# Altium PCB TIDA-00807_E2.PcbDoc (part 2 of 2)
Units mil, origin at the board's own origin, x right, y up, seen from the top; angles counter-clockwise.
Board outline 2559.06 x 2559.06 mil, 2 copper layers (Top Layer, Bottom Layer), stack 62 mil thick; 165 components, 78 nets, 356 pads, 106 vias.
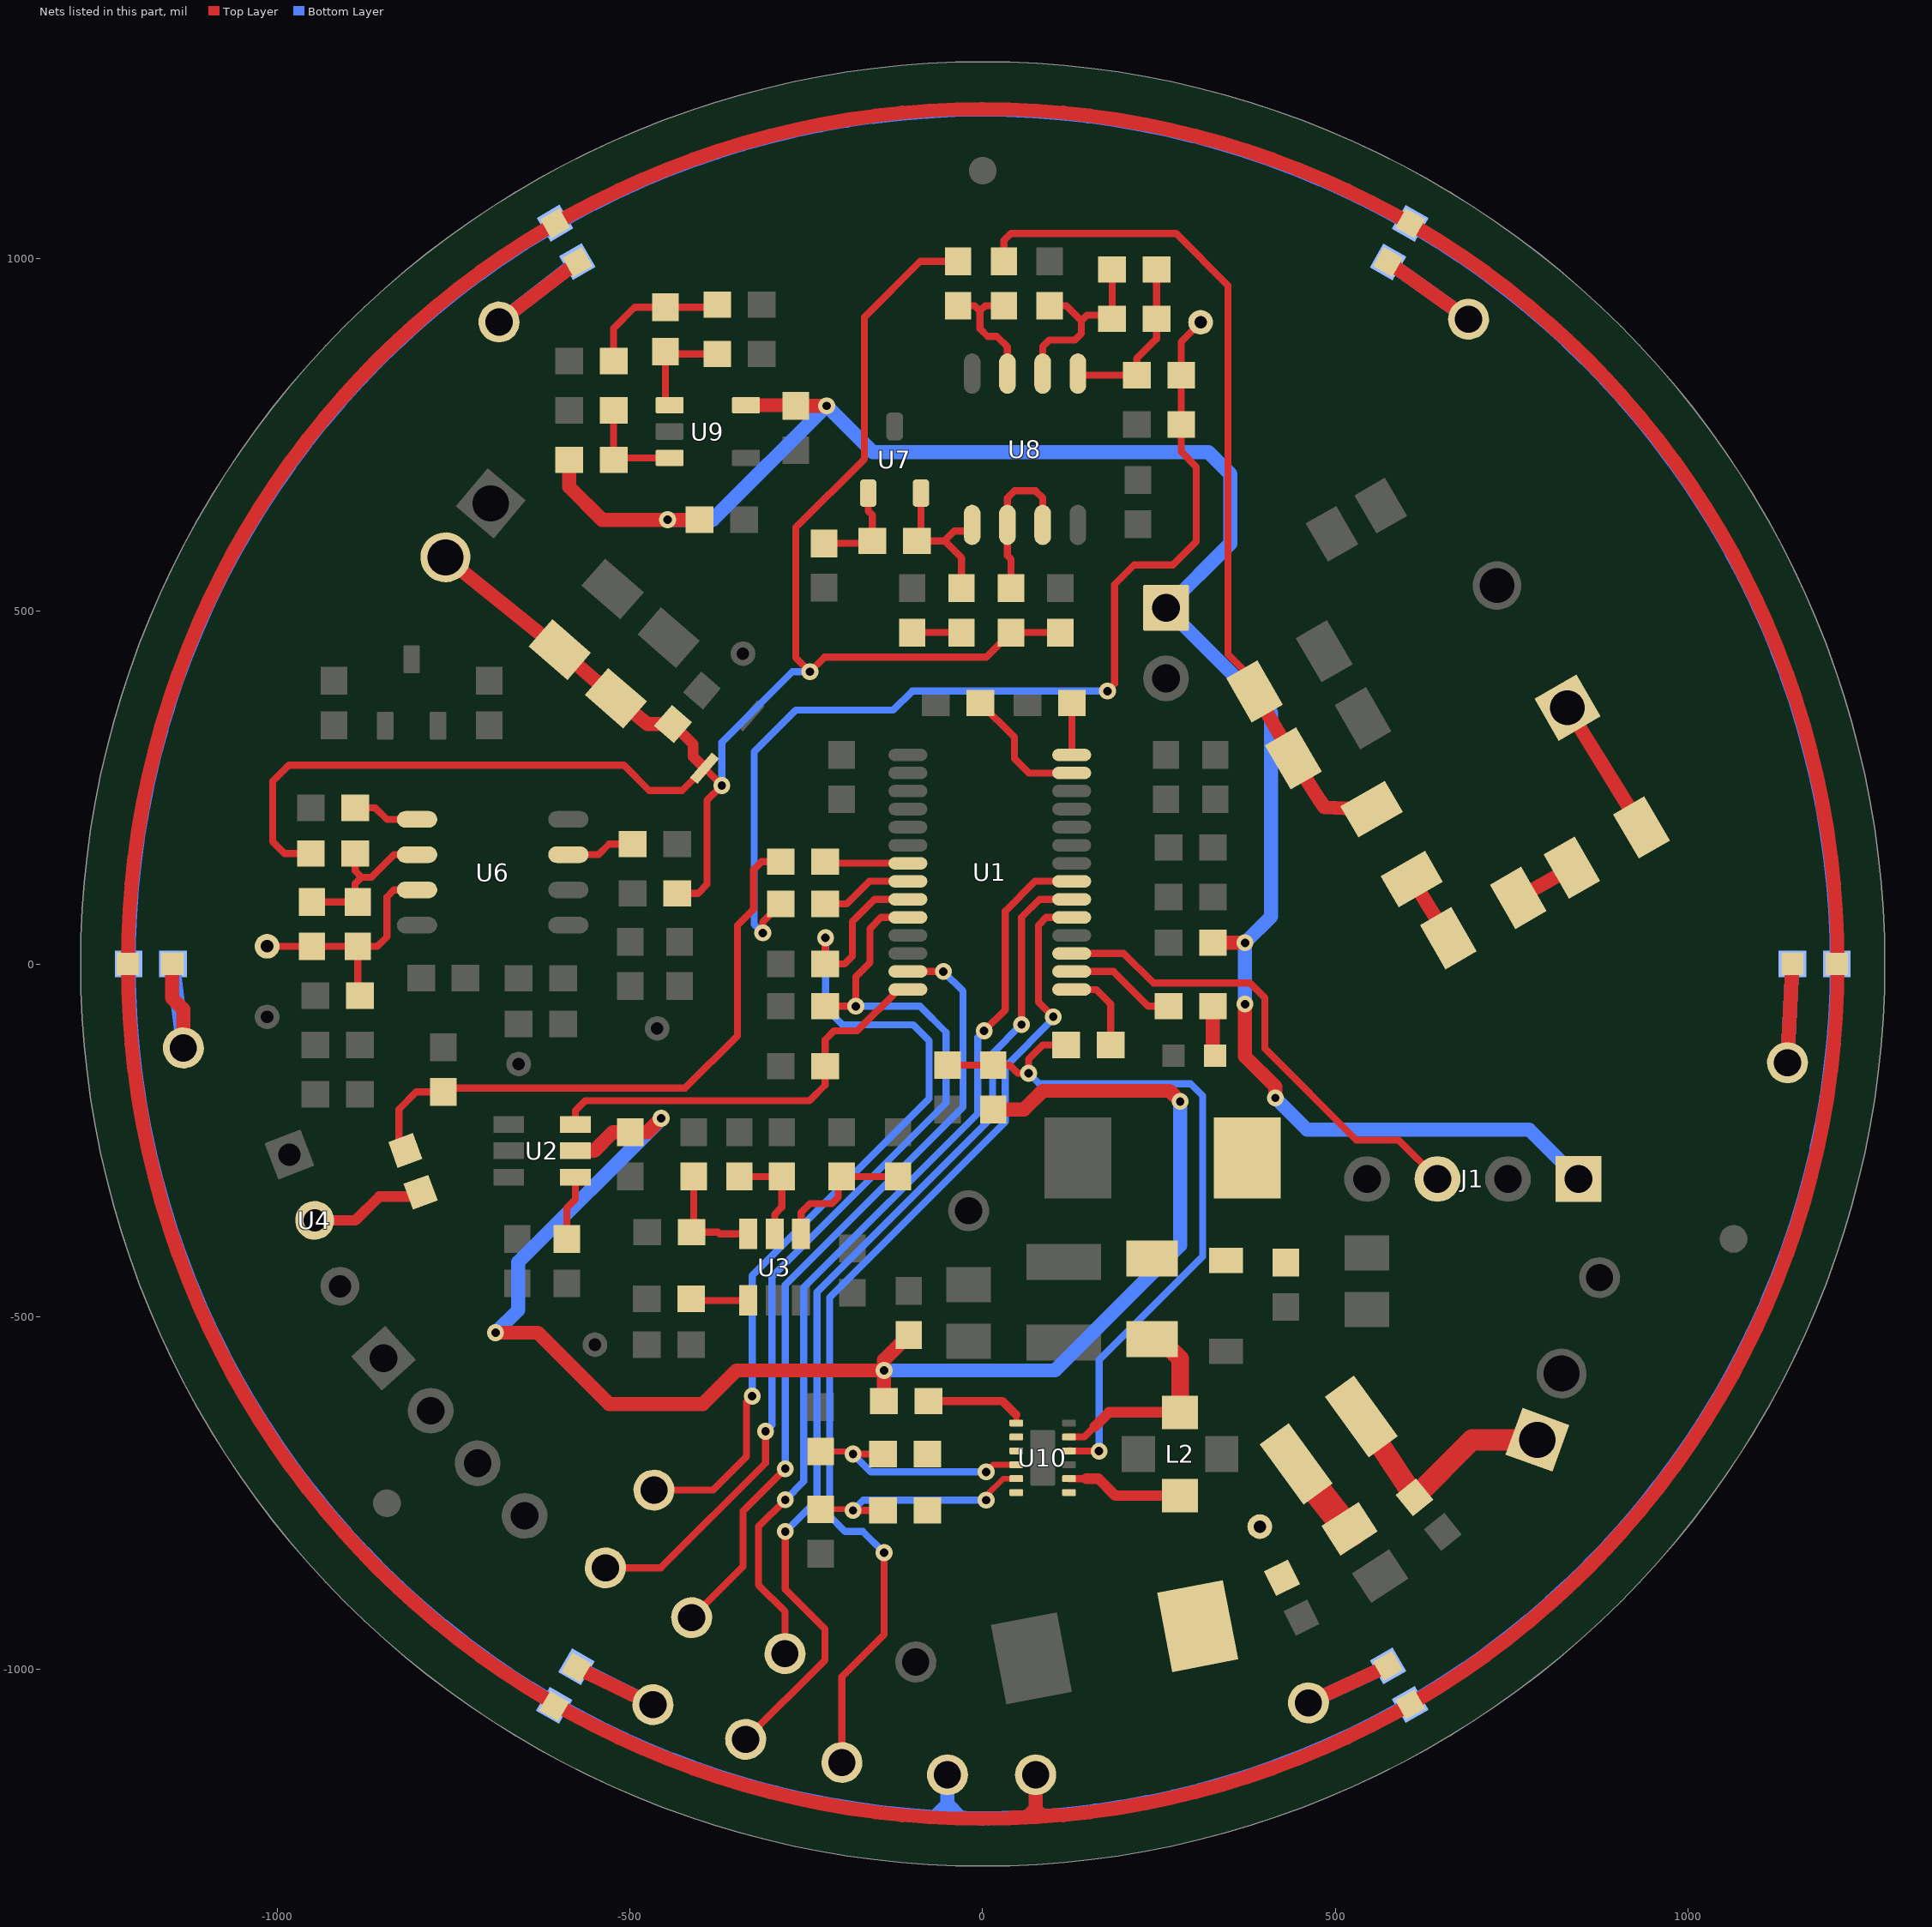
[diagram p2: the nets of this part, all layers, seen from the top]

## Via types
v1: diameter 24, hole 12, Top Layer to Bottom Layer, tented both sides, 103 vias
v2: diameter 19.68, hole 7.87, Top Layer to Bottom Layer, 3 vias

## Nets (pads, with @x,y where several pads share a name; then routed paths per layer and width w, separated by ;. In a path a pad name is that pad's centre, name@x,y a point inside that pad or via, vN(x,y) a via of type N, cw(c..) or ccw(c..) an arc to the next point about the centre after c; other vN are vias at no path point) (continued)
NetC17_1: C17.1 R24.1 R26.2 U6.6 | length 234.6
  Top Layer w10: R24.1@-951.5,87.99 C17.1@-886.5,87.99 -890.2,91.7 -890.2,114 -881.2,123 ; R26.2@-890,156.5 -890,131.8 -881.2,123 ; U6.6@-802.28,155 -835,155 -867,123 -881.2,123
NetC17_2: C17.2 R24.2 R27.1 TP5.1 U6.7 | length 350.2
  Top Layer w10: TP5.1@-1015,25 R24.2@-951.5,25 C17.2@-886.5,25 ; R27.1@-883.5,-45 -886.5,-42.01 C17.2@-886.5,25 ; U6.7@-802.28,105 -835,105 -845,95 -845,38.5 -858.5,25 C17.2@-886.5,25
NetC19_1: C19.1 R31.2 R35.1 U8.2 | length 291.9
  Top Layer w10: U8.2@85,837.28 85,875.8 94.2,885 131,885 140,894 140,912 ; R35.1@95,933.5 118.5,933.5 140,912 ; R31.2@183.5,985 C19.1@183.5,915 178.5,920 148,920 140,912
NetC19_2: C19.2 R31.1 R38.1 U8.1 | length 246
  Top Layer w10: U8.1@135,837.28 137.28,835 R38.1@218.5,835 218.5,858.5 246.5,886.5 C19.2@246.5,915 R31.1@246.5,985
NetC23_1: C23.1 J5.1 L1.1 | length 345.1
  Top Layer w30: L1.1@536.98,-641.97 C23.1@612.65,-756.55 694.24,-674.96 J5.1@786.67,-674.96
NetC24_1: C24.1 C25.1 C26.1 L1.2 R49.2 R50.2 TP8.1 U10.1 U10.8 U10.9 U10.12 | length 124.8
  Top Layer w40: L1.2@444.62,-709.08 518.33,-802.35 C25.1@522,-807
NetD1_1: D1.1 R3.2 | length 71.3
  Top Layer w20: R3.2@326.5,-60 326.5,-126.97 D1.1@329.53,-130
NetD4_1: D4.1 R55.2 TP20.1 | length 280.3
  Top Layer w20: D4.1@574.8,995.59 TP20.1@689.08,914.44
  Bottom Layer w20: R55.2@574.8,995.59 TP20.1@689.08,914.44
NetD4_2: D4.2 D5.2 D6.2 D7.2 D8.2 D9.2 TP19.1 | length 7739.8
  Top Layer w20: 42.28,-1210.76 ccw(c0,0) 63.4,-1209.84 74.21,-1199.04 75,-1199.04 ; TP19.1@75,-1150 75,-1199.04 ; 105.59,-1206.89 cw(c0,0) 84.51,-1208.54 75,-1199.04 ; D5.2@1212.6,0 ccw(c0,0) D5.2@1212.6,0
NetD5_1: D5.1 R56.2 TP21.1 | length 280.7
  Top Layer w20: TP21.1@1141.43,-140.15 D5.1@1148.5,0
  Bottom Layer w20: TP21.1@1141.43,-140.15 R56.2@1148.5,0
NetD6_1: D6.1 R57.2 TP22.1 | length 248.8
  Top Layer w20: TP22.1@462,-1048 D6.1@574.8,-995.59
  Bottom Layer w20: TP22.1@462,-1048 R57.2@574.8,-995.59
NetD7_1: D7.1 R58.2 TP23.1 | length 241.7
  Top Layer w20: D7.1@-576.25,-998.1 TP23.1@-467.75,-1050.58
  Bottom Layer w20: R58.2@-576.3,-996.7 TP23.1@-467.75,-1050.58
NetD8_1: D8.1 R59.2 TP24.1 | length 245.8
  Top Layer w20: D8.1@-1149.61,0 -1149.61,-48.49 -1133.76,-64.35 TP24.1@-1133.76,-119.16
  Bottom Layer w20: R59.2@-1148.5,0 TP24.1@-1133.76,-119.16
NetD9_1: D9.1 R60.2 TP25.1 | length 280.3
  Top Layer w20: TP25.1@-686.07,910.44 D9.1@-574.8,995.59
  Bottom Layer w20: TP25.1@-686.07,910.44 R60.2@-575.05,996.01
NetJ1_3: J1.3 U1.17 | length 693.5
  Top Layer w10: U1.17@126.14,14.84 200.16,14.84 242,-27 379,-27 400,-48 400,-120 530,-250 590,-250 J1.3@645,-305
NetJ4_1: J4.1 R34.1 | length 199.7
  Top Layer w20: J4.1@829.42,363.4 R34.1@934.44,193.54
NetL2_2: L2.2 U10.2 | length 167.6
  Top Layer w10: U10.2@122.4,-730 147,-730
  Top Layer w15: 147,-730 164,-730 188.05,-754.05 L2.2@280,-754.05
NetL2_4: L2.4 R48.1 U10.5 | length 299.6
  Top Layer w10: U10.5@122.4,-670.94 144.06,-670.94 159,-656
  Top Layer w15: 159,-656 179.06,-635.94 L2.4@280,-635.94
  Top Layer w25: R48.1@240,-532.09 252.09,-532.09 280,-560 L2.4@280,-635.94
NetR3_1: R3.1 U1.16 | length 157.8
  Top Layer w10: U1.16@126.14,-10.75 185.75,-10.75 235,-60 R3.1@263.5,-60
NetR4_1: R4.1 R8.2 U3.5 | length 145.4
  Top Layer w10: R4.1@-345,-301.5 R8.2@-285,-301.5 -285,-345 -295,-355 U3.5@-295,-382.76
NetR5_1: R5.1 R10.2 U3.4 | length 201.2
  Top Layer w10: U3.4@-257.6,-382.76 -257.6,-352.6 -245,-340 -214,-340 -205,-331 R10.2@-205,-301.5 ; R10.2@-200,-301.5 R5.1@-120,-301.5
NetR7_1: R7.1 U3.1 | length 82
  Top Layer w10: R7.1@-413.5,-475 -411.26,-477.24 U3.1@-332.4,-477.24
NetR9_1: R9.1 U4.2 | length 166.8
  Top Layer w15: U4.2@-947.58,-363.74 -889.74,-363.74 -856,-330 -803.63,-330 R9.1@-797.36,-323.73
NetR11_2: R11.2 R12.2 U3.6 | length 161.6
  Top Layer w10: R11.2@-410,-301.5 -410,-377.65 R12.2@-412.86,-380.51 -375.51,-380.51 -373.27,-382.76 U3.6@-332.4,-382.76
NetR15_2: R15.2 R19.2 | length 70
  Top Layer w10: R15.2@-100,470 R19.2@-30,470
NetR18_2: R18.2 U6.3 | length 97.4
  Top Layer w10: U6.3@-587.72,155 -545,155 -530,170 R18.2@-496.5,170
NetR20_1: R20.1 U8.6 U8.7 | length 226.6
  Top Layer w10: R20.1@40,532.99 40,574 35,579 U8.6@35,622.72 35,661 45,671 75,671 85,661 U8.7@85,622.72
NetR21_1: R21.1 R25.2 U7.1 | length 140.2
  Top Layer w10: R25.2@-225,596.5 -160,596.5 R21.1@-156.5,600 -156.5,636.5 -162.4,642.4 U7.1@-162.4,667.76
NetR28_2: R28.2 U6.5 | length 94.5
  Top Layer w10: R28.2@-890,221.5 -861.5,221.5 -845,205 U6.5@-802.28,205
NetR29_2: R29.2 R33.1 U9.3 | length 150.4
  Top Layer w10: R29.2@-523.5,785 R33.1@-523.5,715 -520.91,717.6 U9.3@-444.13,717.6
NetR30_1: R30.1 R39.2 R41.1 R42.1 | length 1232.1
  Top Layer w10: R39.2@30,996.5 30,1025.98 40.02,1036 274,1036 348,962 348,439 385.56,401.44 R41.1@385.56,386.46
  Top Layer w20: R41.1@385.56,386.46 R42.1@440.56,291.46 478,232 485,222 R30.1@551.46,219.44
NetR30_2: R30.2 R32.2 | length 98.9
  Top Layer w20: R30.2@608.54,120.56 R32.2@660.56,36.46
NetR32_1: R32.1 R34.2 | length 87.4
  Top Layer w20: R32.1@759.44,93.54 R34.2@835.56,136.46
NetR36_1: R36.1 R40.1 R44.2 | length 207.4
  Top Layer w10: R36.1@-523.5,855 -523.5,901.5 -493.5,931.5 R40.1@-450,931.5 -380,931.5 R44.2@-376.5,935
NetR39_1: R39.1 R43.1 U8.3 | length 183.7
  Top Layer w10: R43.1@-35,933.5 -11.5,933.5 -4,926 ; R39.1@30,933.5 3.5,933.5 -4,926 ; U8.3@35,837.28 35,875 20,890 7,890 -4,901 -4,926
NetR40_2: R40.2 R46.1 U9.1 | length 153.5
  Top Layer w10: U9.1@-444.13,792.4 -450,798.27 R40.2@-450,868.5 -446.5,865 R46.1@-376.5,865
NetR45_1: R45.1 U1.7 | length 122.2
  Top Layer w10: R45.1@-228.5,140 R45.1@-225.71,142.8 ; R45.1@-223.5,145 -221.3,142.8 U1.7@-106.14,142.8
NetR49_1: R49.1 R53.2 U10.11 | length 342.5
  Top Layer w8: R53.2@-230,-773.5 -185.5,-773.5 v1(-184,-775) ; v1@5,-760 5,-754.24 29.24,-730 U10.11@47.6,-730
  Top Layer w10: v1(-184,-775) R49.1@-141.5,-775
  Bottom Layer w10: v1(-184,-775) -169.47,-760.47 v1(5,-760.47)
NetR50_1: R50.1 R54.2 U10.10 | length 336.1
  Top Layer w8: R54.2@-230,-691.5 -187.5,-691.5 v1(-184,-695) ; v1@5,-720 14.69,-710.31 U10.10@47.6,-710.31
  Top Layer w10: v1(-184,-695) R50.1@-141.5,-695
  Bottom Layer w10: v1(-184,-695) -158.53,-720.47 v1(5,-720.47)
NetR55_1: R55.1 R56.1 R57.1 R58.1 R59.1 R60.1 TP18.1 | length 7791.7
  Bottom Layer w20: -84.51,-1208.54 ccw(c0,0) -67.81,-1209.6 ; TP18.1@-50,-1150 -50,-1191.79 ; -4.41,-1211.49 cw(c0,0) -25.55,-1211.23 ; -67.81,-1209.6 cw(c0,0) R56.1@1211.5,0 cw(c0,0) -67.81,-1209.6 ; -67.81,-1209.6 ccw(c0,0) -46.69,-1210.6 ccw(c0,0) -30.68,-1211.11 ; -67.81,-1209.6 -50,-1191.79 ; -50,-1191.79 -30.68,-1211.11 ; -30.68,-1211.11 ccw(c0,0) -25.55,-1211.23 ; -30.68,-1211.11 -30.56,-1211.23 -25.55,-1211.23
NetR62_2: R62.2 U2.4 | length 92.7
  Top Layer w10: R62.2@-590,-390 -590,-346 -577.76,-333.76 U2.4@-577.76,-302.4
NetR63_1: R63.1 U1.8 | length 130.7
  Top Layer w10: R63.1@-223.5,85 -193,85 -160.8,117.2 U1.8@-106.14,117.2
NetR64_1: R64.1 U1.27 | length 195.5
  Top Layer w10: R64.1@-8.5,375 R64.1@-3.5,370 45,321.5 45,291.26 65.51,270.75 U1.27@126.14,270.75
NetR65_1: R65.1 U1.28 | length 78.8
  Top Layer w10: U1.28@126.14,296.34 126.5,296.69 R65.1@126.5,375
NetR66_1: R66.1 U1.15 | length 122.2
  Top Layer w10: U1.15@126.14,-36.34 161.34,-36.34 181.5,-56.5 R66.1@181.5,-115
NetR67_2: R67.2 TP11.1 U1.9 | length 1334.9
  Top Layer w10: TP11.1@-466.33,-746.28 -382.28,-746.28 -335,-699 -335,-621 v1(-327,-613) ; v1(-223,37) -223.5,36.5 R67.2@-223.5,0 -196,0 -185,11 -185,60 -153.39,91.61 U1.9@-106.14,91.61
  Bottom Layer w10: v1(-327,-613) -327,-442 -76,-191 -76,-109 -98.69,-86.31 -198.69,-86.31 -223,-62 v1(-223,37)
NetR68_2: R68.2 TP12.1 U1.10 | length 1371.4
  Top Layer w10: TP12.1@-535.22,-856.53 -456.53,-856.53 -308,-708 v1(-308,-663) ; R68.2@-223.5,-60 v1(-180,-60) -180,-18 -160,2 -160,50 -143.98,66.02 U1.10@-106.14,66.02
  Bottom Layer w10: v1(-308,-663) -299,-654 -299,-444 -52,-197 -52,-97 -89,-60 v1(-180,-60)
NetTP10_1: TP10.1 U1.13 | length 1137.8
  Top Layer w10: TP10.1@-412.84,-927.25 -340,-854.41 -340,-776 v1(-280,-716) ; U1.13@-106.14,-10.75 v1(-55.75,-10.75)
  Bottom Layer w10: v1(-280,-716) -280,-455 -28,-203 -28,-38.5 v1(-55.75,-10.75)
NetTP13_1: TP13.1 U1.19 | length 1450.5
  Top Layer w10: TP13.1@-199.7,-1132.53 -199.7,-1010.7 -140,-951 v1(-140,-835) ; v1(100,-75) 79,-54 79,55 90.02,66.02 U1.19@126.14,66.02
  Bottom Layer w10: v1(-140,-835) -170,-805 -195,-805 -217,-783 -217,-472.91 32,-223.91 32,-146 100,-78 v1(100,-75)
NetTP14_1: TP14.1 U1.20 | length 1456.1
  Top Layer w10: TP14.1@-336.23,-1099.75 -223.83,-987.35 -223.83,-943.27 -280,-887.1 v1(-280,-805) ; v1(55,-86) 55,66 80.61,91.61 U1.20@126.14,91.61
  Bottom Layer w10: v1(-280,-805) -235,-760 -235,-465.46 14,-216.46 14,-127 v1(55,-86)
NetTP15_1: TP15.1 U1.21 | length 1327.6
  Top Layer w10: TP15.1@-280.69,-978.31 TP15.1@-279,-980 ; TP15.1@-280.46,-978.08 -280.46,-918.54 -318,-881 -318,-798 v1(-280,-760) ; v1(2,-95) 32,-65 32,75 74.2,117.2 U1.21@126.14,117.2
  Bottom Layer w10: v1(-280,-760) -254,-734 -254,-459 -7,-212 -7,-104 v1(2,-95)
PG: R47.1 U10.7 | length 144.5
  Top Layer w8: U10.7@47.6,-651.26 47.6,-639.4
  Top Layer w12: R47.1@-77.01,-620 28.2,-620 47.6,-639.4
PS_CONTROL: R61.1 R66.2 R69.1 U10.4 | length 1072.9
  Top Layer w10: R61.1@-50,-143.5 R69.1@15,-143.5 R69.1@18.5,-143.5 ; R69.1@20,-145 R69.1@18.5,-143.5 ; R66.2@120,-115 R66.2@118.5,-115 85,-115 65,-135 v1(65,-155) 50,-155 38.5,-143.5 R69.1@18.5,-143.5 ; U10.4@122.4,-690.63 U10.4@124.66,-690.63 ; U10.4@124.66,-691 v1(165,-691)
  Bottom Layer w10: v1(65,-155) 80,-170 295,-170 312,-187 312,-415 165,-562 v1(165,-691)
TEMP: C9.2 R9.2 R45.2 | length 874
  Top Layer w10: R9.2@-818.91,-264.54 -828,-255.45 -828,-206 -803.5,-181.5 C9.2@-765,-181.5 -759.5,-176 -422,-176 -348,-102 -348,55 -325,78 -325,134 -314,145 R45.2@-286.5,145
TEST_SEL: R1.1 U1.14 U2.6 | length 600.1
  Top Layer w10: U2.6@-577.76,-227.6 -577.76,-207.76 -564,-194 -245.7,-194 -223.5,-171.8 R1.1@-223.5,-145 -223.5,-107.5 -211,-95 -178,-95 -119.34,-36.34 U1.14@-106.14,-36.34
V1: C22.2 R38.2 R63.2 TP7.1 | length 1477.9
  Top Layer w10: v1(-312,44) -312,59.5 R63.2@-286.5,85 ; v1(177,387) 187,397 187,538 215,566 270,566 303,599 303,705 281.5,726.5 C22.2@281.5,765 R38.2@281.5,835 281.5,882.5 TP7.1@309,910
  Bottom Layer w10: v1(-312,44) -324,56 -324,301 -265,360 -127,360 -100,387 v1(177,387)
VCC: C6.1 C21.2 C28.1 C29.1 D3.1 J1.1 JP2.1 R2.2 R33.2 R37.2 R47.2 R48.2 R51.2 R69.2 U2.5 U9.5 | length 5045.4
  Top Layer w20: v1(-691,-523) -631,-523 -530,-624 -396.81,-624 -349.31,-576.5 v1(-140,-576.5) ; R33.2@-586.5,715 -586.5,676.5 -540,630 v1(-447,630) R37.2@-401.5,630 ; U2.5@-577.76,-265 -551,-265 -524.5,-238.5 C6.1@-500,-238.5 -475.5,-238.5 v1(-456,-219) ; U9.5@-335.87,792.4 -265.91,792.4 C21.2@-265,791.5 v1(-221.5,791.5) ; R47.2@-140,-620 v1(-140,-576.5) ; R51.2@-105,-526.5 -140,-561.5 v1(-140,-576.5) ; R69.2@15,-206.5 58.5,-206.5 85,-180 265,-180 v1(280,-195) ; R2.2@326.5,30 v1(372,30) ; v1(372,-57) 372,-131 415,-174 v1(415,-190)
  Bottom Layer w20: v1(-691,-523) -659,-491 -659,-423 -456,-220 v1(-456,-219) ; v1(-447,630) -383,630 v1(-221.5,791.5) -156.01,726 320,726 351,695 351,596 JP2.1@260,505 409,356 409,67 v1(372,30) v1(372,-57) ; v1(-140,-576.5) 102.5,-576.5 280,-399 v1(280,-195) ; v1(415,-190) 460,-235 775,-235 J1.1@845,-305
VCC_C/2: C15.2 C16.2 D2.2 J3.2 R16.1 R20.2 R22.1 R23.1 R26.1 R43.2 | length 2839.6
  Top Layer w10: R26.1@-952.99,156.5 -990,156.5 -1007,173.5 -1007,259 -984,282 -509,282 -473,246 -426.31,246 D2.2@-394.55,277.77 v1(-370,253.06) -391,232.06 -391,113 -404,100 R16.1@-433.5,100 ; R43.2@-35,996.5 -88.5,996.5 -168,917 -168,716 -265,619 -265,434.27 v1(-245.18,414.45) -224.63,435 5,435 R20.2@40,470 C15.2@110,470
  Top Layer w15: C16.2@-439.53,340.34 -411,311.82 -411,294.22 D2.2@-394.55,277.77
  Top Layer w20: J3.2@-762.14,576.7 R22.1@-599.71,445.68 R23.1@-520.47,376.79 -475,340 C16.2@-439.53,340.34
  Bottom Layer w10: v1(-370,253.06) -370,314.4 -269.95,414.45 v1(-245.18,414.45)
VREF: R19.1 R21.2 U7.2 U8.5 | length 237.9
  Top Layer w10: U7.2@-87.6,667.76 -87.6,605.91 R21.2@-93.5,600 -54,600 ; R19.1@-30,532.99 -30,576 -54,600 ; U8.5@-17,620.72 U8.5@-15,622.72 -23.72,614 -40,614 -54,600
pads on no net: FID1.1 FID2.1 FID3.1 FID4.1 FID5.1 FID6.1 L2.1 L2.3 U1.1 U1.2 U1.11 U1.12 U10.13@85,-678.82 U10.13@85,-722.13

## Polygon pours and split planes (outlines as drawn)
NetC24_1 on Top Layer "TOP_LAYER_NETC24_1_P001" (solid, remove dead copper, pour order 1): -85,-665 -90,-665 -95,-670 -95,-815 -95,-865 -75,-885 170,-885 175,-885 200,-910 205,-915 205,-985 205,-1020 247.5,-1062.5 357.09,-1025.97 370,-1008.06 370,-921.36 455,-875 570,-800 530,-740 435,-805 400,-770 365,-770 325,-810 170,-810 130,-770 35,-770 35,-790 20,-805 -10,-805 -35,-780 -35,-700 -30,-695 -30,-670 -35,-665
VCC on Top Layer "TOP_LAYER_VCC_P004" (solid, remove dead copper, pour order 4): 230.94,-335 305,-335 315,-325 315,-235 305,-225 275,-225 265,-215 265,-185 270,-180 355,-180 425,-180 475,-230 475,-420 455,-440 225,-440 210,-425 210,-355.95
GND on Bottom Layer "BOTTOM_LAYER_GND_P000" (solid, remove dead copper, pour order 0): -289,296 -289,25 -305,25 -315,15 -315,-127.54 -292.54,-150 335,-150 385,-100 385,90 385,260 305,340 -245,340
DGND on Bottom Layer "BOTTOM_LAYER_DGND_P008" (solid, remove dead copper, pour order 8): 723.64,796.37 799.57,720.45 cw(c69.72,21.53) 1080,-0.99 1080,-18.91 cw(c61.9,-18.92) 1002.5,-408.54 cw(c67.41,-21.23) 783.09,-736.91 719.57,-800.43 cw(c71.75,-152.61) 422.34,-999.03 414.4,-1002.32 cw(c23.88,-59.52) 23.87,-1080 -58.08,-1080 cw(c-58.08,-189.83) -398.73,-1012.24 cw(c45.8,60.95) -775.59,-760.43 -781.41,-754.62 cw(c-111.28,-84.49) -986.84,-447.16 -995.68,-425.83 cw(c27.8,-1.9) -1080,-1.91 -1080,43.66 cw(c-154.82,43.66) -1000.72,418.37 cw(c-14.23,-18.61) -739.2,780.47 -629.5,880 -430.89,993.87 cw(c2.07,-51.32) 2.09,1080 33.73,1080 cw(c38.88,111.62)

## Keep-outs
Keep-Out Layer:
  circle w10: c0,0 r1259.84
  text ".Layer_Name" at -1723,-2858.49 h60

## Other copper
Top Layer:
  region net NetC24_1: 35,-750 40,-745 55,-745 60,-750 60,-785 35,-785
  region net NetC24_1: 110,-750 115,-745 130,-745 135,-750 135,-780 110,-780
  region net NetC24_1: 55,-670 50,-665 -45,-665 -45,-695 50,-695 55,-690
  text ".Layer_Name" at -1723,-2858.49 h60
Bottom Layer:
  pour cut-out: 745,680 620.18,599.82 555,705 338,560 338,317.64 434.49,221.15 434.49,-14.49 500,-80 1078.23,-80 1079.39,-78.84 1079.39,440.62 807.3,712.71
  text ".Layer_Name" at -1723,-2858.49 h60

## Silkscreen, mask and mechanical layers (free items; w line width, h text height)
Top Overlay:
  circle w10: c-845,290 r10
  circle w10: c-560,15 r7.07
  circle w10: c155,-750 r10
  circle w10: c-155,295 r7.07
  circle w10: c135,885 r7.07
  circle w10: c-475,820 r7.07
  lines w6: -1092,49 -1041,49 ; -1004,-172 -1004,-169 -983,-148 ; -566.63,-47.51 -553.49,-47.51 -526,-75 ; -331,-40 -386,-40 ; -221,-569 -188,-569 -177,-580 ; 280,945 325,945 ; -1041,49 -1041,48 -1047,42 -1047,55 -1041,49 ; -386,-40 -380,-46 -380,-34 -386,-40
  text "E2" at -860,745 h108.27 r60
  text ".PRJ_Number" at -1132,282 h108.27 r60
  text ".Layer_Name" at -1723,-2858.49 h60
Bottom Overlay:
  text ".Layer_Name" at -1723,-2858.49 h60
Top Paste:
  text ".Layer_Name" at -1723,-2858.49 h60
Bottom Paste:
  text ".Layer_Name" at -1723,-2858.49 h60
Top Solder:
  text ".Layer_Name" at -1723,-2858.49 h60
  text ".Layer_Name" at -1723,-2858.49 h60
Bottom Solder:
  text ".Layer_Name" at -1723,-2858.49 h60
Drill Guide:
  text ".Layer_Name" at -1723,-2858.49 h60
M1 Board Outline:
  circle w10: c0,0 r1279.53
M2 Board Dimensions:
  rectangle: -2175,-2400 -1800,-2275
  rectangle: -2300,-2275 -2175,-2150
  lines w7: -2300,-2275 -1300,-2275 ; -2175,-2400 -2175,-2150 ; -2050,-2400 -2050,-2150 ; -1800,-2400 -1800,-2150 ; -1550,-2400 -1550,-2150 ; -2300,-2400 -2300,-2150 -1300,-2150 -1300,-2400 -2300,-2400
M3 3D STEP Top:
  text ".Layer_Name" at -1723,-2858.49 h60
M4 3D STEP Bottom:
  text ".Layer_Name" at -1723,-2858.49 h60
M5 Assembly Top:
  circle w10: c-163,652 r6.71
  circle w10: c-945,-272.07 r7.07
  circle w10: c-847,306 r11.18
  circle w10: c-465,790 r7.07
  circle w10: c-332,-478.54 r6.77
  circle w10: c-845,-565 r13.26
  circle w10: c850,-304 r11.66
  circle w10: c710.2,-626 r17.02
  lines w6: -355,-356.02 -354.09,-355.11 -235,-355.11 -235,-505 -240,-505 -331,-505 -355,-505 -355,-355.11
  lines w10: -2592,-2930.17 4008,-2930.17 ; -2592,-2726.83 4010,-2726.83 ; -2592,-2523.5 -2592,-3133.5 1413,-3133.5 4010,-3133.5 4010,-2523.5 -2591.5,-2523.5 -2591.5,-3133.5 -1016,-3133.5 ; -127,-3133.5 -127,-2523.5 ; 1140,-2726.83 1140,-2523.5 ; 1980,-2726.83 1980,-2523.5 ; 2602,-3140 2602,-2937.17
  text "COMPONENTS MARKED 'DNP' SHOULD NOT BE POPULATED." at -1146.5,-2318.5 h60
  text "ASSEMBLY VARIANT:" at -1147,-2434 h60
  text ".VariantName" at -111,-2434 h60
  text "PCB VIEWED FROM TOP SIDE" at -2528.5,-2655.67 h60
  text "BOARD #:" at -52,-2655.67 h60
  text ".PRJ_Number" at 493.5,-2655.67 h60
  text "REV:" at 1338,-2655.67 h60
  text ".PCB_Rev" at 1629.5,-2655.67 h60
  text "SVN REV:" at 2176,-2655.67 h60
  text ".VersionControl_RevNumber" at 2682,-2655.67 h60
  text ".Layer_Name" at -1723,-2858.49 h60
  text "TID #:" at -52,-2859 h60
  text ".TID" at 493.5,-2859 h60
  text "LAYER NAME =" at -2525.5,-2862.34 h60
  text "PLOT NAME =" at -2528.5,-3064.34 h60
  text ".plot_File_Name" at -1723,-3064.34 h60
  text "GENERATED    :" at -50,-3064.34 h60
  text ".Print_Date" at 819.5,-3064.34 h60
  text ".Print_Time" at 1548.5,-3064.34 h60
  text "TEXAS INSTRUMENTS" at 2813,-3064.34 h60
M6 Assembly Bottom:
  lines w10: -2592.5,-2727.33 4009.5,-2727.33 ; -2590.5,-2930.67 4009.5,-2930.67 ; -1184.5,-3140.5 -1184.5,-2937.67 ; -562.5,-2727.33 -562.5,-2524 ; 277.5,-2727.33 277.5,-2524 ; 1544.5,-3134 1544.5,-2524 ; 2433.5,-3134 4009,-3134 4009,-2524 -2592.5,-2524 -2592.5,-3134 4.5,-3134 4009.5,-3134 4009.5,-2524
  text "COMPONENTS MARKED 'DNP' SHOULD NOT BE POPULATED." at 3802,-2318 h60
  text ".VariantName" at 2758,-2434 h60
  text "ASSEMBLY VARIANT:" at 3797,-2434 h60
  text ".VersionControl_RevNumber" at -1264.5,-2656.17 h60
  text "SVN REV:" at -758.5,-2656.17 h60
  text ".PCB_Rev" at -212,-2656.17 h60
  text "REV:" at 79.5,-2656.17 h60
  text ".PRJ_Number" at 924,-2656.17 h60
  text "BOARD #:" at 1469.5,-2656.17 h60
  text "PCB VIEWED FROM BOTTOM SIDE" at 3946,-2656.17 h60
  text ".Layer_Name" at 3132,-2852 h60
  text "LAYER NAME =" at 3939,-2855.84 h60
  text ".TID" at 924,-2859.5 h60
  text "TID #:" at 1469.5,-2859.5 h60
  text "TEXAS INSTRUMENTS" at -1395.5,-3064.84 h60
  text ".Print_Time" at -131,-3064.84 h60
  text ".Print_Date" at 598,-3064.84 h60
  text "GENERATED    :" at 1467.5,-3064.84 h60
  text ".plot_File_Name" at 3140.5,-3064.84 h60
  text "PLOT NAME =" at 3946,-3064.84 h60
M9 Title Sheet:
  drawing of 57 lines, arcs and shapes, not listed
  text "1" at -1560.16,6036.5 h70
  text "2" at 935.5,6036.5 h70
  text "3" at 3424.84,6036.5 h70
  text "4" at 5931.51,6036.5 h70
  text "5" at 8430.5,6036.5 h70
  text "6" at 10935.5,6036.5 h70
  text "A" at -2716.5,4893.5 h70
  text "A" at 12083.5,4893.5 h70
  text "B" at -2716.5,2513.5 h70
  text "B" at 12083.5,2513.5 h70
  text "C" at -2716.5,138.5 h70
  text "C" at 12083.5,138.5 h70
  text "PROJECT TITLE:" at 9043.5,-1722.5 h45
  text ".PRJ_Title" at 9093.5,-1855.83 h70
  text "DESIGNED FOR:" at 9043.5,-2023.5 h45
  text ".PRJ_Customer" at 9093.5,-2163.5 h70
  text "D" at -2716.5,-2231.5 h70
  text "D" at 12083.5,-2231.5 h70
  text "FILE NAME:" at 9043.5,-2323.5 h45
  text ".PCB_File_Name_No_Path" at 9093.5,-2443.5 h70
  text "Texas Instruments (TI) and/or its licensors do not warrant the accuracy or completeness of this specification" at 4074,-2605.34 h45
  text "ENGINEER:" at 9043.5,-2613.5 h45
  text "LAYOUT BY:" at 10548.5,-2613.5 h45
  text "or any information contained therein. TI and/or its licensors do not warrant that this design will meet" at 4029.01,-2718 h45
  text ".PRJ_Engineer" at 9093.5,-2768.49 h70
  text ".PCB_Layout" at 10599,-2768.49 h70
  text "the specifications, will be suitable for your application or fit for any particular purpose, or will operate in" at 4029.01,-2830.67 h45
  text "ALTIUM DESIGNER VERSION:" at 10548.5,-2923.5 h45
  text "an implementation. TI and/or its licensors do not warrant that the design is production worthy. You should" at 4029.01,-2943.33 h45
  text "completely validate and test your design implementation to confirm the system functionality for your application." at 4074,-3056 h45
  text ".print_Scale" at 9093.5,-3056.83 h70
  text ".Application_BuildNumber" at 10599,-3056.83 h70
  text "1" at -1560.16,-3263.5 h70
  text "2" at 935.5,-3263.5 h70
  text "3" at 3424.84,-3263.5 h70
  text "4" at 5931.51,-3263.5 h70
  text "5" at 8430.5,-3263.5 h70
  text "6" at 10935.5,-3263.5 h70
M10 Fab Notes:
  drawing of 189 lines, arcs and shapes, not listed
  text "DESIGN INFORMATION" at 10078.02,4201 h60
  text "MIN. TRACK WIDTH:" at 9433.46,4021 h60
  text "8" at 10529.7,4021 h60
  text "MIL" at 10708,4021 h60
  text "MIL" at 10709,3903 h60
  text "7.874" at 10410,3894 h60
  text "MIN. CLEARANCE:" at 9433.46,3889 h60
  text "MIL" at 10713,3763 h60
  text "19.69" at 10418,3759 h60
  text "MIN. VIA PAD SIZE:" at 9433.46,3757 h60
  text "EXTERNAL" at 11072,3616 h60
  text "0.15mm (5.9055 MIL)" at 10128.46,3615.29 h60
  text "MINIMUM ANNULAR RING" at 9104.23,3611 h60
  text "PER" at 9304.23,3493 h60
  text "IPC-D-275 CLASS 2 LEVEL C" at 9524.23,3493 h60
  text "MIL, HOLES" at 11012.46,3380.71 h60
  text "+/-" at 10620,3380 h60
  text "+/-" at 11474,3380 h60
  text "REGISTRATION TOLERANCES:" at 9104.23,3375 h60
  text "METAL" at 10304,3375 h60
  text "5" at 10880.2,3375 h60
  text "3" at 11713.2,3375 h60
  text "MIL" at 11829.46,3375 h60
  text "+/-" at 11474,3262 h60
  text "HOLE SIZE TOLERANCE (UNLESS OTHERWISE SPECIFIED):" at 9104.23,3257 h60
  text "3" at 11713.2,3257 h60
  text "MIL" at 11829.46,3257 h60
  text "MATERIAL:" at 9029.46,3047.54 h60
  text "FR-4 High Tg" at 10015.9,2907.21 h60
  text "FR-408" at 9450.46,2898.64 h60
  text "OTHER" at 10938.46,2898.64 h60
  text "X" at 9861,2895 h60
  text "63 MIL (1.6mm) +/-10%" at 9770.56,2735.92 h60
  text "THICKNESS:" at 9104.23,2731.64 h60
  text "X" at 9642.4,2731.64 h60
  text "OTHER" at 11055.46,2731.64 h60
  text "TOLERANCE:" at 9104.23,2573.64 h60
  text "X" at 9943.53,2573.64 h60
  text "ANSI IPC-6012 TYPE 3 CLASS 2" at 10130.48,2573.64 h60
  text "OTHER +/-" at 10130.46,2417.64 h60
  text "BOW & TWIST:" at 9104.23,2260.64 h60
  text "X" at 9943.53,2260.64 h60
  text "ANSI IPC-6012 TYPE 3 CLASS 2" at 10130.48,2260.64 h60
  text "OTHER +/-" at 10130.46,2102.13 h60
  text "DRILLING:" at 9029.46,1963.64 h60
  text "REFERENCE:" at 9104.23,1846.64 h60
  text "X" at 9752.46,1846.64 h60
  text "AS SHOWN" at 9939.46,1846.64 h60
  text "X" at 10653.46,1846.64 h60
  text "NC_DRILL FILES" at 10790.46,1846.64 h60
  text "PTH COPPER THICKNESS:" at 9104.23,1688.64 h60
  text "X" at 10234.46,1688.64 h60
  text "20-30 um" at 10371.46,1688.64 h60
  text "OTHER" at 11088.46,1688.64 h60
  text "BOARD FINISH:" at 9029.46,1529.64 h60
  text "SILKSCREEN:" at 9184.68,1411.64 h60
  text "X" at 10133.46,1411.64 h60
  text "TOP" at 10259.46,1411.64 h60
  text "X" at 10643.46,1411.64 h60
  text "BOTTOM" at 10770.46,1411.64 h60
  text "SILKSCREEN COLOR:" at 9184.68,1244.64 h60
  text "X" at 10132.42,1244.64 h60
  text "WHITE" at 10259.46,1244.64 h60
  text "OTHER" at 10770.46,1244.64 h60
  text "X" at 10263.42,1085.44 h60
  text "GREEN" at 10390.46,1085.44 h60
  text "OTHER" at 11008.46,1085.44 h60
  text "SOLDER RESIST COLOR:" at 9184.68,1074.64 h60
  text "X" at 10263.42,915.44 h60
  text "MATTE" at 10390.46,915.44 h60
  text "SEMI-GLOSS" at 11008,914.8 h60
  text "IMMERSION GOLD (ENIG)" at 10090.46,726.92 h60
  text "ENEPIG" at 11428,723.64 h60
  text "SURFACE FINISH:" at 9029.46,722.64 h60
  text "X" at 9903.51,722.64 h60
  text "IMM. TIN/SILVER OR EQUIV" at 9359,565.64 h60
  text "OTHER" at 10790.46,565.64 h60
  text "ARRAY/PANEL:" at 9029.46,386.64 h60
  text "CUT AND TRIM PER M1 BOARD OUTLINE" at 10090.46,382.35 h60
  text "N.C. ROUTE" at 10090.46,230.64 h60
  text "X" at 10769.46,230.64 h60
  text "V. SCORE" at 10956.46,230.64 h60
  text "CERTIFICATION:" at 9029.46,93.64 h60
  text "MATERIALS AND WORKMANSHIP FOR ALL PCBS" at 9754.46,93.64 h60
  text "TO MEET OR EXCEED THE REQUIREMENTS OF:" at 9754.46,-4.36 h60
  text "X" at 9380.96,-140.87 h60
  text "ANSI IPC-A-600F CLASS ->" at 9519.96,-140.87 h60
  text "X" at 11159.02,-140.87 h60
  text "2" at 11277.96,-140.86 h60
  text "1" at 10962.96,-142.36 h60
  text "3" at 11631.96,-142.36 h60
  text "X" at 10195.02,-300.36 h60
  text "RoHS" at 10331.96,-300.36 h60
  text "OTHER" at 10976.36,-300.36 h60
  text "PER ORDER" at 11373.42,-300.36 h60
  text "ALL BOARDS MUST MEET OR EXCEED UL94-V0 REQUIREMENTS." at 9057,-466 h60
  text "PCB MUST BEAR THE UL94V-0 UL REGISTERED MATERIAL ID NUMBER" at 9057,-586 h60
  text "VIA TENTING:" at 10188,-736 h60
  text "X" at 10948,-738 h60
  text "YES" at 10737.67,-745.08 h60
  text "NO" at 11102.47,-750.31 h60
  text "ADDITIONAL REQUIREMENTS:" at 9029.46,-759.36 h60
  text "IMPEDANCE CONTROL:" at 10210,-865 h60
  text "YES" at 11194,-866 h60
  text "X" at 11736,-873 h60
  text "MICROSECTION:" at 9104.23,-874.36 h60
  text "YES" at 10009.96,-874.36 h60
  text "NO" at 11569.47,-883.31 h60
  text "REQUIRED" at 10871.46,-1030.51 h60
  text "BARE BOARD ELEC. TEST:" at 9104.23,-1033.36 h60
  text "NONE" at 10409.96,-1033.36 h60
  text "X" at 10744.46,-1033.36 h60
  text "PER ORDER" at 11463.46,-1033.36 h60
M11 Gerber Information:
  lines w10: -2592,-2930.17 4008,-2930.17 ; -2592,-2726.83 4010,-2726.83 ; -2592,-2523.5 -2592,-3133.5 1413,-3133.5 4010,-3133.5 4010,-2523.5 -2591.5,-2523.5 -2591.5,-3133.5 -1016,-3133.5 ; -127,-3133.5 -127,-2523.5 ; 1140,-2726.83 1140,-2523.5 ; 1980,-2726.83 1980,-2523.5 ; 2602,-3140 2602,-2937.17
  text "ALL ARTWORK VIEWED FROM TOP SIDE" at -2528.5,-2655.67 h60
  text "BOARD #:" at -52,-2655.67 h60
  text ".PRJ_Number" at 493.5,-2655.67 h60
  text "REV:" at 1338,-2655.67 h60
  text ".PCB_Rev" at 1629.5,-2655.67 h60
  text "SVN REV:" at 2176,-2655.67 h60
  text ".VersionControl_RevNumber" at 2682,-2655.67 h60
  text "LAYER NAME =" at -2528.5,-2858.49 h60
  text "TID #:" at -52,-2859 h60
  text ".TID" at 493.5,-2859 h60
  text "PLOT NAME =" at -2528.5,-3064.34 h60
  text ".plot_File_Name" at -1723,-3064.34 h60
  text "GENERATED    :" at -50,-3064.34 h60
  text ".Print_Date" at 819.5,-3064.34 h60
  text ".Print_Time" at 1548.5,-3064.34 h60
  text "TEXAS INSTRUMENTS" at 2813,-3064.34 h60
M12 Stackup:
  drawing of 191 lines, arcs and shapes, not listed
  text "Layer" at 7525.34,5865 h60
  text "Name" at 7935.26,5865 h60
  text "Material" at 8865,5865 h60
  text "Thickness" at 9724.77,5865 h60
  text "Constant" at 10374.6,5865 h60
  text "Board Layer Stack" at 10944.46,5865 h60
  text "1" at 7525.34,5745 h60
  text "Top Overlay" at 7935.26,5745 h60
  text "2" at 7525.34,5625 h60
  text "Top Solder" at 7935.26,5625 h60
  text "Solder Resist" at 8865,5625 h60
  text "0.40mil" at 9724.77,5625 h60
  text "3.5" at 10374.6,5625 h60
  text "3" at 7525.34,5505 h60
  text "Top Layer" at 7935.26,5505 h60
  text "Copper" at 8865,5505 h60
  text "1.40mil" at 9724.77,5505 h60
  text "4" at 7525.34,5385 h60
  text "Dielectric1" at 7935.26,5385 h60
  text "FR-4 High Tg" at 8865,5385 h60
  text "59.20mil" at 9724.77,5385 h60
  text "4.8" at 10374.6,5385 h60
  text "5" at 7525.34,5265 h60
  text "Bottom Layer" at 7935.26,5265 h60
  text "Copper" at 8865,5265 h60
  text "1.40mil" at 9724.77,5265 h60
  text "6" at 7525.34,5145 h60
  text "Bottom Solder" at 7935.26,5145 h60
  text "Solder Resist" at 8865,5145 h60
  text "0.40mil" at 9724.77,5145 h60
  text "3.5" at 10374.6,5145 h60
  text "7" at 7525.34,5025 h60
  text "Bottom Overlay" at 7935.26,5025 h60
M13 Component Bodies Top:
  text ".Layer_Name" at -1723,-2858.49 h60
M14 Component Bodies Bottom:
  text ".Layer_Name" at -1723,-2858.49 h60
M15 Courtyards Top:
  text ".Layer_Name" at -1723,-2858.49 h60
M16 Courtyards Bottom:
  text ".Layer_Name" at -1723,-2858.49 h60
Drill Drawing:
  circle w10: c3063.8,270.41 r16.59
  circle w10: c3063.8,270.41 r27.66
  lines w10: 3036.14,367.21 3036.14,381.04 3049.97,394.87 3036.14,408.7 3036.14,422.52 3049.97,422.52 3063.8,408.7 3077.63,422.52 3091.46,422.52 3091.46,408.7 3077.63,394.87 3091.46,381.04 3091.46,367.21 3077.63,367.21 3063.8,381.04 3049.97,367.21 3036.14,367.21 ; 3036.14,505.5 3049.97,505.5 3063.8,491.67 3077.63,505.5 3091.46,505.5 3077.63,519.33 3091.46,533.15 3077.63,533.15 3063.8,546.98 3049.97,533.15 3036.14,533.15 3049.97,519.33 3036.14,505.5 ; 3036.14,629.96 3049.97,629.96 3049.97,616.13 3077.63,616.13 3077.63,629.96 3091.46,629.96 3091.46,657.61 3077.63,657.61 3077.63,671.44 3049.97,671.44 3049.97,657.61 3036.14,657.61 3036.14,629.96 ; 3036.14,740.59 3091.46,740.59 3091.46,795.9 3036.14,795.9 3036.14,740.59 ; 3036.14,920.36 3091.46,920.36 3063.8,865.04 3036.14,920.36 ; 3036.14,989.5 3063.8,1003.33 3091.46,989.5 3077.63,1017.16 3091.46,1044.82 3063.8,1030.99 3036.14,1044.82 3049.97,1017.16 3036.14,989.5 ; 3036.14,1113.96 3091.46,1113.96 3091.46,1169.28 3036.14,1169.28 3036.14,1113.96 ; 3036.14,1266.08 3063.8,1238.42 3091.46,1266.08 3063.8,1293.74 3036.14,1266.08 ; 3047.21,751.65 3080.39,751.65 3080.39,784.84 3047.21,784.84 3047.21,751.65
  lines w12: 2986,205.41 4965.4,205.41 ; 2986,1325.54 4965.4,1325.54 ; 3324.17,80.95 3324.17,1450 ; 3656.28,80.95 3656.28,1450 ; 4293.29,80.95 4293.29,1450 ; 4552.64,80.95 4552.64,1450 ; 2986,80.95 4965.4,80.95 4965.4,1450 2986,1450 2986,80.95
  text "Symbol" at 3060.68,1362.88 h72
  text "Quantity" at 3361.51,1362.88 h72
  text "Finished Hole Size" at 3693.62,1362.88 h72
  text "Plated" at 4330.62,1362.88 h72
  text "Hole Type" at 4589.98,1362.88 h72
  text "3" at 3361.51,1238.42 h60
  text "7.87mil (0.200mm)" at 3693.62,1238.42 h60
  text "PTH" at 4330.62,1238.42 h60
  text "Round" at 4589.98,1238.42 h60
  text "101" at 3361.51,1113.96 h60
  text "12.00mil (0.305mm)" at 3693.62,1113.96 h60
  text "PTH" at 4330.62,1113.96 h60
  text "Round" at 4589.98,1113.96 h60
  text "8" at 3361.51,989.5 h60
  text "17.72mil (0.450mm)" at 3693.62,989.5 h60
  text "PTH" at 4330.62,989.5 h60
  text "Round" at 4589.98,989.5 h60
  text "3" at 3361.51,865.04 h60
  text "31.50mil (0.800mm)" at 3693.62,865.04 h60
  text "PTH" at 4330.62,865.04 h60
  text "Round" at 4589.98,865.04 h60
  text "17" at 3361.51,740.59 h60
  text "38.50mil (0.978mm)" at 3693.62,740.59 h60
  text "PTH" at 4330.62,740.59 h60
  text "Round" at 4589.98,740.59 h60
  text "8" at 3361.51,616.13 h60
  text "39.37mil (1.000mm)" at 3693.62,616.13 h60
  text "PTH" at 4330.62,616.13 h60
  text "Round" at 4589.98,616.13 h60
  text "2" at 3361.51,491.67 h60
  text "40.00mil (1.016mm)" at 3693.62,491.67 h60
  text "PTH" at 4330.62,491.67 h60
  text "Round" at 4589.98,491.67 h60
  text "2" at 3361.51,367.21 h60
  text "49.21mil (1.250mm)" at 3693.62,367.21 h60
  text "PTH" at 4330.62,367.21 h60
  text "Round" at 4589.98,367.21 h60
  text "4" at 3361.51,242.75 h60
  text "51.18mil (1.300mm)" at 3693.62,242.75 h60
  text "PTH" at 4330.62,242.75 h60
  text "Round" at 4589.98,242.75 h60
  text "148 Total" at 3361.51,118.29 h60
  text "FOR 7.87MIL DRILL +0/-7.87MIL" at 2993,-348 h60
  text "FOR 12MIL DRILL +0/-12MIL" at 2993,-462 h60
  text "FOR PTH DRILL +/-3MIL" at 2993,-568 h60
  text ".Layer_Name" at -1723,-2858.49 h60
M17 Embedded Cavity:
  text ".Layer_Name" at -1723,-2858.49 h60
M18 Embedded Assembly:
  text ".Layer_Name" at -1723,-2858.49 h60
M19 Embedded Keepout:
  text ".Layer_Name" at -1723,-2858.49 h60

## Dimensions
0,0 to 1611,723 on M2 Board Dimensions
-1279.53,0 to 1279.53,0 on M2 Board Dimensions
-2300,-2400 to -1300,-2400 on M2 Board Dimensions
